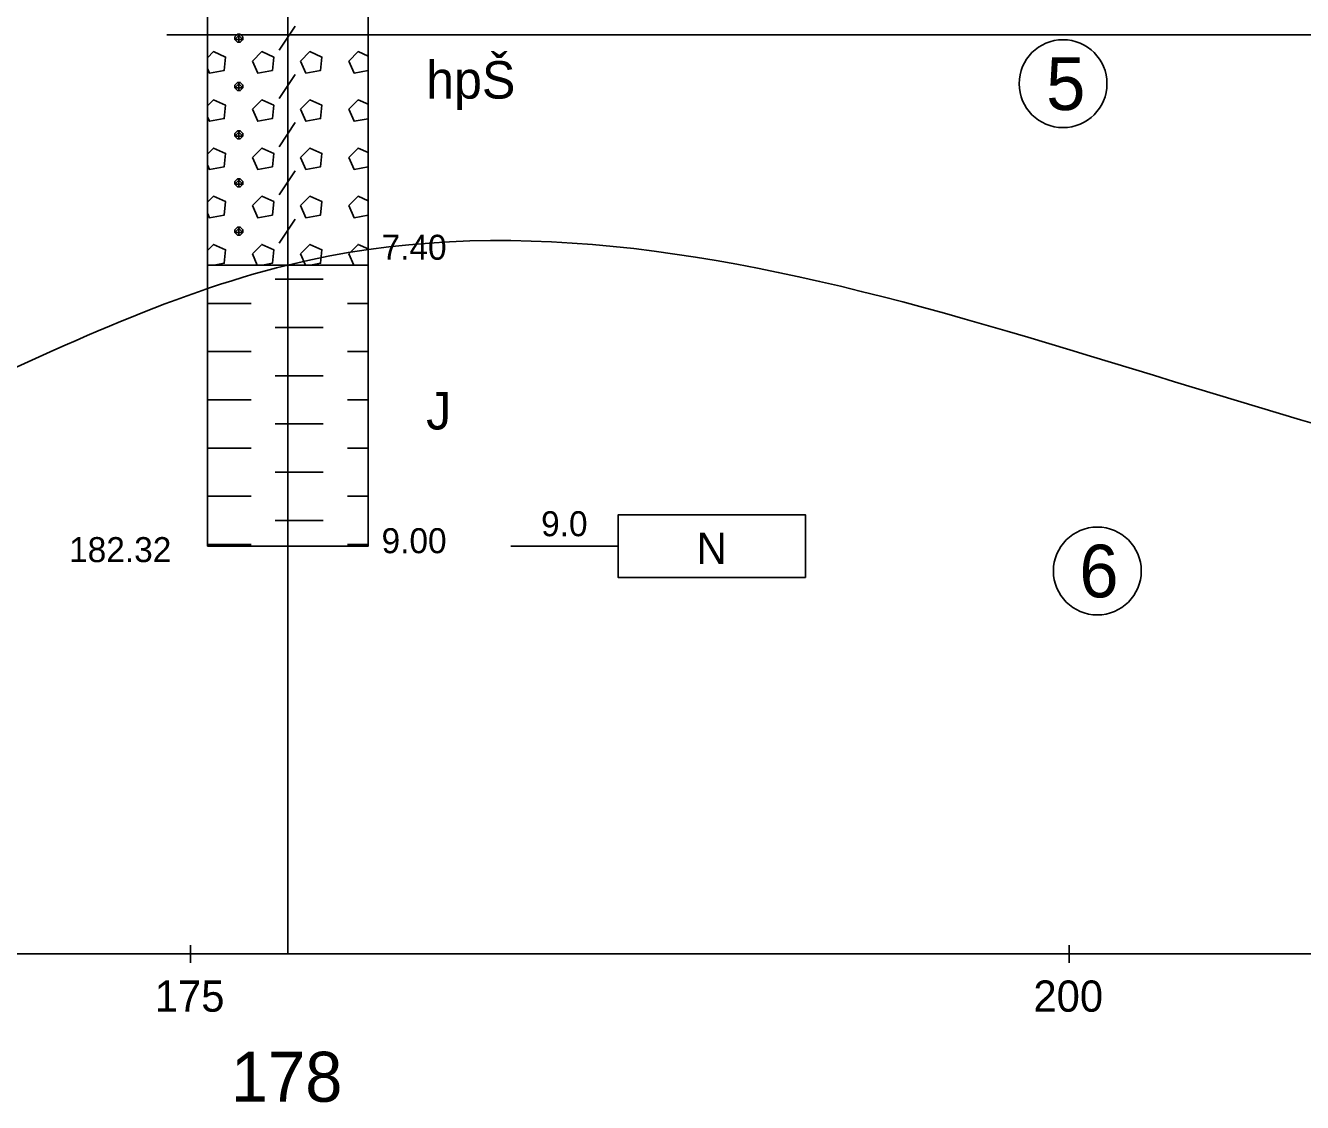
# Model space of a CAD drawing. Extents: x 3042 to 4120, y 576 to 2694.
# Drawn here: x 3417.6 to 3453.93, y 579.6 to 610.24 of the extents above; entities that cross this region are included whole.
import ezdxf

# ---------------------------------------------------------------- set-up
doc = ezdxf.new("R2010")
doc.units = 0
for name, color, linetype in [('14', 7, 'Continuous'), ('17', 7, 'Continuous'), ('18', 7, 'Continuous'), ('51', 7, 'Continuous'), ('52', 7, 'Continuous'), ('53', 7, 'Continuous'), ('56', 7, 'Continuous'), ('62', 7, 'Continuous'), ('7', 7, 'Continuous'), ('rozhraní', 7, 'Continuous')]:
    doc.layers.add(name, color=color, linetype=linetype)

msp = doc.modelspace()

# ---------------------------------------------------------------- linework, layer by layer
at = {"layer": '18'}
for p, q in [((3425.062, 583.826), (3425.062, 640.427)), ((3425.062, 595.808), (3425.062, 595.046)), ((3424.681, 595.427), (3425.443, 595.427)), ((3425.062, 584.207), (3425.062, 583.826))]:
    msp.add_line(p, q, dxfattribs=at)
at = {"layer": '51'}
for p, q in [((3424.815, 609.536), (3425.272, 610.222)), ((3423.672, 609.765), (3423.672, 609.994)), ((3423.672, 608.393), (3423.672, 608.622)), ((3424.815, 608.165), (3425.272, 608.851)), ((3424.815, 606.793), (3425.272, 607.479)), ((3423.672, 607.022), (3423.672, 607.25)), ((3424.815, 605.422), (3425.272, 606.107)), ((3423.672, 605.65), (3423.672, 605.879)), ((3424.815, 604.05), (3425.272, 604.736)), ((3423.672, 604.279), (3423.672, 604.507)), ((3424.053, 603.745), (3424.194, 603.426)), ((3425.424, 603.745), (3425.566, 603.427)), ((3426.796, 603.745), (3426.938, 603.427)), ((3424.7, 603.021), (3425.386, 603.021)), ((3425.386, 603.021), (3426.072, 603.021)), ((3422.776, 602.336), (3423.329, 602.336)), ((3423.329, 602.336), (3424.015, 602.336)), ((3426.758, 602.336), (3427.348, 602.336)), ((3424.7, 601.65), (3425.386, 601.65)), ((3425.386, 601.65), (3426.072, 601.65)), ((3422.776, 600.964), (3423.329, 600.964)), ((3423.329, 600.964), (3424.015, 600.964)), ((3426.758, 600.964), (3427.348, 600.964)), ((3424.7, 600.278), (3425.386, 600.278)), ((3425.386, 600.278), (3426.072, 600.278)), ((3422.776, 599.592), (3423.329, 599.592)), ((3423.329, 599.592), (3424.015, 599.592)), ((3426.758, 599.592), (3427.348, 599.592)), ((3424.7, 598.907), (3425.386, 598.907)), ((3425.386, 598.907), (3426.072, 598.907)), ((3422.776, 598.221), (3423.329, 598.221)), ((3423.329, 598.221), (3424.015, 598.221)), ((3426.758, 598.221), (3427.348, 598.221)), ((3424.7, 597.535), (3425.386, 597.535)), ((3425.386, 597.535), (3426.072, 597.535)), ((3422.776, 596.849), (3423.329, 596.849)), ((3423.329, 596.849), (3424.015, 596.849)), ((3426.758, 596.849), (3427.348, 596.849)), ((3424.7, 596.163), (3425.386, 596.163)), ((3425.386, 596.163), (3426.072, 596.163)), ((3422.776, 595.478), (3423.329, 595.478)), ((3423.329, 595.478), (3424.015, 595.478)), ((3426.758, 595.478), (3427.348, 595.478))]:
    msp.add_line(p, q, dxfattribs=at)
for points in [[(3422.776, 603.427), (3427.348, 603.427), (3427.348, 616.427), (3422.776, 616.427)], [(3422.776, 595.427), (3427.348, 595.427), (3427.348, 603.427), (3422.776, 603.427)]]:
    msp.add_lwpolyline(points, close=True, dxfattribs=at)
for points in [[(3423.634, 609.994), (3423.557, 609.917), (3423.557, 609.841), (3423.634, 609.765), (3423.71, 609.765), (3423.786, 609.841), (3423.786, 609.917), (3423.71, 609.994), (3423.634, 609.994), (3423.786, 609.841), (3423.557, 609.841), (3423.71, 609.994)], [(3422.776, 609.019), (3422.833, 608.889), (3423.253, 608.965), (3423.291, 609.346), (3422.948, 609.498), (3422.776, 609.326)], [(3424.053, 609.232), (3424.205, 608.889), (3424.624, 608.965), (3424.662, 609.346), (3424.319, 609.498), (3424.053, 609.232)], [(3425.424, 609.232), (3425.577, 608.889), (3425.996, 608.965), (3426.034, 609.346), (3425.691, 609.498), (3425.424, 609.232)], [(3427.348, 609.372), (3427.063, 609.498), (3426.796, 609.232)], [(3426.796, 609.232), (3426.948, 608.889), (3427.348, 608.961)], [(3423.634, 608.622), (3423.557, 608.546), (3423.557, 608.47), (3423.634, 608.393), (3423.71, 608.393), (3423.786, 608.47), (3423.786, 608.546), (3423.71, 608.622), (3423.634, 608.622), (3423.786, 608.47), (3423.557, 608.47), (3423.71, 608.622)], [(3422.776, 607.647), (3422.833, 607.517), (3423.253, 607.593), (3423.291, 607.974), (3422.948, 608.127), (3422.776, 607.955)], [(3424.053, 607.86), (3424.205, 607.517), (3424.624, 607.593), (3424.662, 607.974), (3424.319, 608.127), (3424.053, 607.86)], [(3425.424, 607.86), (3425.577, 607.517), (3425.996, 607.593), (3426.034, 607.974), (3425.691, 608.127), (3425.424, 607.86)], [(3427.348, 608), (3427.063, 608.127), (3426.796, 607.86)], [(3426.796, 607.86), (3426.948, 607.517), (3427.348, 607.59)], [(3423.634, 607.25), (3423.557, 607.174), (3423.557, 607.098), (3423.634, 607.022), (3423.71, 607.022), (3423.786, 607.098), (3423.786, 607.174), (3423.71, 607.25), (3423.634, 607.25), (3423.786, 607.098), (3423.557, 607.098), (3423.71, 607.25)], [(3422.776, 606.275), (3422.833, 606.146), (3423.253, 606.222), (3423.291, 606.603), (3422.948, 606.755), (3422.776, 606.583)], [(3424.053, 606.488), (3424.205, 606.146), (3424.624, 606.222), (3424.662, 606.603), (3424.319, 606.755), (3424.053, 606.488)], [(3425.424, 606.488), (3425.577, 606.146), (3425.996, 606.222), (3426.034, 606.603), (3425.691, 606.755), (3425.424, 606.488)], [(3427.348, 606.628), (3427.063, 606.755), (3426.796, 606.488)], [(3426.796, 606.488), (3426.948, 606.146), (3427.348, 606.218)], [(3423.634, 605.879), (3423.557, 605.803), (3423.557, 605.726), (3423.634, 605.65), (3423.71, 605.65), (3423.786, 605.726), (3423.786, 605.803), (3423.71, 605.879), (3423.634, 605.879), (3423.786, 605.726), (3423.557, 605.726), (3423.71, 605.879)], [(3422.776, 604.904), (3422.833, 604.774), (3423.253, 604.85), (3423.291, 605.231), (3422.948, 605.384), (3422.776, 605.212)], [(3424.053, 605.117), (3424.205, 604.774), (3424.624, 604.85), (3424.662, 605.231), (3424.319, 605.384), (3424.053, 605.117)], [(3425.424, 605.117), (3425.577, 604.774), (3425.996, 604.85), (3426.034, 605.231), (3425.691, 605.384), (3425.424, 605.117)], [(3427.348, 605.257), (3427.063, 605.384), (3426.796, 605.117)], [(3426.796, 605.117), (3426.948, 604.774), (3427.348, 604.847)], [(3423.634, 604.507), (3423.557, 604.431), (3423.557, 604.355), (3423.634, 604.279), (3423.71, 604.279), (3423.786, 604.355), (3423.786, 604.431), (3423.71, 604.507), (3423.634, 604.507), (3423.786, 604.355), (3423.557, 604.355), (3423.71, 604.507)], [(3422.966, 603.427), (3423.253, 603.479), (3423.291, 603.86), (3422.948, 604.012), (3422.776, 603.84)], [(3424.338, 603.427), (3424.624, 603.479), (3424.662, 603.86), (3424.319, 604.012), (3424.053, 603.745)], [(3425.709, 603.427), (3425.996, 603.479), (3426.034, 603.86), (3425.691, 604.012), (3425.424, 603.745)], [(3427.348, 603.885), (3427.063, 604.012), (3426.796, 603.745)]]:
    msp.add_lwpolyline(points, dxfattribs=at)
at = {"layer": '53'}
for p, q in [((3422.776, 640.427), (3422.776, 595.427)), ((3427.348, 640.427), (3427.348, 595.427)), ((3422.776, 603.427), (3427.348, 603.427)), ((3422.776, 595.427), (3427.348, 595.427))]:
    msp.add_line(p, q, dxfattribs=at)
at = {"layer": '56'}
for p, q in [((3425.062, 603.808), (3425.062, 603.046)), ((3424.681, 603.427), (3425.443, 603.427)), ((3425.062, 595.808), (3425.062, 595.046)), ((3424.681, 595.427), (3425.443, 595.427))]:
    msp.add_line(p, q, dxfattribs=at)
at = {"layer": '62'}
msp.add_line((3431.412, 595.427), (3434.46, 595.427), dxfattribs=at)
msp.add_lwpolyline([(3439.794, 594.538), (3434.46, 594.538), (3434.46, 596.316), (3439.794, 596.316), (3439.794, 594.538)], dxfattribs=at)
at = {"layer": '7'}
for p, q in [((3422.292, 583.572), (3422.292, 584.08)), ((3447.292, 583.572), (3447.292, 584.08)), ((3247.292, 583.826), (3535.82, 583.826))]:
    msp.add_line(p, q, dxfattribs=at)
at = {"layer": 'rozhraní'}
msp.add_line((3523.782, 609.974), (3421.616, 609.974), dxfattribs=at)
for centre in [(3447.12, 608.587), (3448.095, 594.721)]:
    msp.add_circle(centre, 1.25, dxfattribs=at)
msp.add_spline([(3359.638, 602.832), (3380.358, 602.832), (3404.892, 596.256), (3425.062, 603.427), (3462.842, 596.877), (3513.612, 601.576), (3524.22, 601.576)], degree=3, dxfattribs=at)

# ---------------------------------------------------------------- texts
at = {"layer": '14'}
msp.add_text('178', height=1.4224, dxfattribs=at).set_placement((3423.442, 579.62))
at = {"layer": '17'}
msp.add_text('182.32', height=0.7112, dxfattribs=at).set_placement((3418.839, 594.974))
at = {"layer": '52'}
for s, height, p in [('hpŠ', 1.0668, (3428.999, 608.162)), ('7.40', 0.7112, (3427.729, 603.577)), ('J', 1.067, (3428.999, 598.748)), ('9.00', 0.7112, (3427.729, 595.228))]:
    msp.add_text(s, height=height, dxfattribs=at).set_placement(p)
at = {"layer": '62'}
for s, height, p in [('9.0', 0.7112, (3432.269, 595.711)), ('N', 0.889, (3436.693, 594.925))]:
    msp.add_text(s, height=height, dxfattribs=at).set_placement(p)
at = {"layer": '7'}
for s, p in [('175', (3421.276, 582.182)), ('200', (3446.276, 582.182))]:
    msp.add_text(s, height=0.889, dxfattribs=at).set_placement(p)
at = {"layer": 'rozhraní'}
for s, p in [('5', (3446.639, 607.837)), ('6', (3447.583, 593.971))]:
    msp.add_text(s, height=1.5, dxfattribs=at).set_placement(p)

doc.saveas('drawing.dxf')
